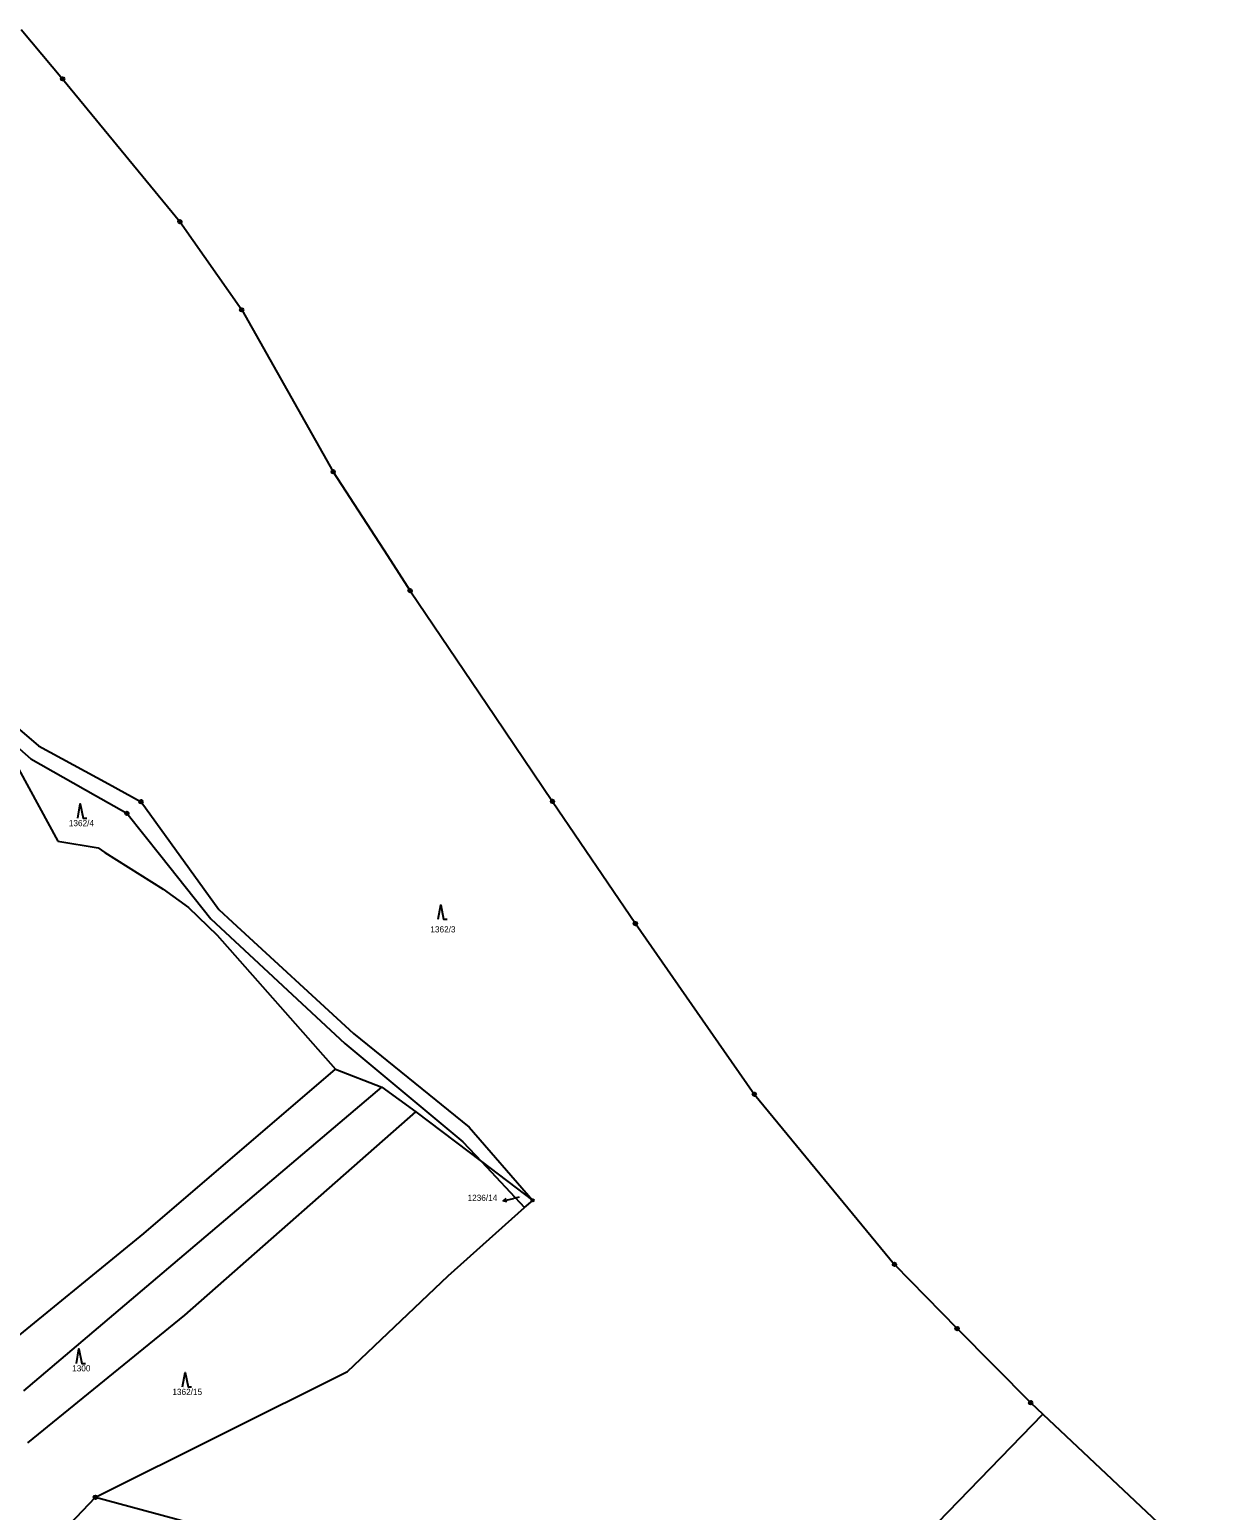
# Model space of a CAD drawing. Extents: x -763205 to -760228, y -1155311 to -1152844.
# Drawn here: x -760828.3 to -760502.3, y -1154305.4 to -1153896.1 of the extents above; entities that cross this region are included whole.
import ezdxf

# ---------------------------------------------------------------- set-up
doc = ezdxf.new("R2010")
doc.units = 0
for name, color, linetype in [('Vrstva 1', 7, 'Continuous'), ('Vrstva 13', 7, 'Continuous'), ('Vrstva 16', 7, 'Continuous'), ('Vrstva 18', 7, 'Continuous'), ('Vrstva 24', 7, 'Continuous'), ('Vrstva 25', 7, 'Continuous'), ('Vrstva 6', 7, 'Continuous')]:
    doc.layers.add(name, color=color, linetype=linetype)

msp = doc.modelspace()

# ---------------------------------------------------------------- linework, layer by layer
at = {"layer": 'Vrstva 1'}
for p, q in [((-760860.08, -1154069.56), (-760827.94, -1154097.7)), ((-760848.01, -1154074.98), (-760825.8, -1154094.1)), ((-760825.8, -1154094.1), (-760806.51, -1154104.61)), ((-760827.94, -1154097.7), (-760810.06, -1154107.81)), ((-760806.51, -1154104.61), (-760797.48, -1154109.54)), ((-760810.06, -1154107.81), (-760801.37, -1154112.73)), ((-760797.48, -1154109.54), (-760775.97, -1154139.3)), ((-760801.37, -1154112.73), (-760792.01, -1154124.48)), ((-760792.01, -1154124.48), (-760778.15, -1154141.89)), ((-760775.97, -1154139.3), (-760772.17, -1154142.8)), ((-760778.15, -1154141.89), (-760741.14, -1154176.34)), ((-760772.17, -1154142.8), (-760738.75, -1154173.58)), ((-760741.14, -1154176.34), (-760708.6, -1154203.49)), ((-760738.75, -1154173.58), (-760706.84, -1154199.49)), ((-760706.84, -1154199.49), (-760689.28, -1154219.7)), ((-760708.6, -1154203.49), (-760703.46, -1154208.97)), ((-760703.46, -1154208.97), (-760691.56, -1154221.65)), ((-760691.56, -1154221.65), (-760689.28, -1154219.7))]:
    msp.add_line(p, q, dxfattribs=at)
at = {"layer": 'Vrstva 13'}
for p, q in [((-760830.59, -1153896.11), (-760819.16, -1153909.72)), ((-760819.16, -1153909.72), (-760786.73, -1153949.18)), ((-760786.73, -1153949.18), (-760769.67, -1153973.56)), ((-760769.67, -1153973.56), (-760744.4, -1154018.31)), ((-760744.4, -1154018.31), (-760729.42, -1154041.48)), ((-760729.42, -1154041.48), (-760723.14, -1154051.19)), ((-760723.14, -1154051.19), (-760699.65, -1154085.96)), ((-760699.65, -1154085.96), (-760683.8, -1154109.44)), ((-760683.8, -1154109.44), (-760660.89, -1154143.21)), ((-760660.89, -1154143.21), (-760636.5, -1154178.24)), ((-760636.5, -1154178.24), (-760628.04, -1154190.4)), ((-760628.04, -1154190.4), (-760589.33, -1154237.4)), ((-760589.33, -1154237.4), (-760572.03, -1154255.15)), ((-760572.03, -1154255.15), (-760551.7, -1154275.64)), ((-760551.7, -1154275.64), (-760548.38, -1154278.77)), ((-760548.38, -1154278.77), (-760502.34, -1154322.12))]:
    msp.add_line(p, q, dxfattribs=at)
at = {"layer": 'Vrstva 16'}
for p in [(-760697.48, -1154219.847), (-760692.97, -1154218.79)]:
    msp.add_line(p, (-760694.56, -1154219.16), dxfattribs=at)
msp.add_lwpolyline([(-760696.392, -1154220.105), (-760697.48, -1154219.847), (-760696.621, -1154219.132)], dxfattribs=at)
at = {"layer": 'Vrstva 24'}
for centre, radius in [((-760819.16, -1153909.72), 0.5), ((-760819.16, -1153909.72), 0.1), ((-760786.73, -1153949.18), 0.5), ((-760786.73, -1153949.18), 0.1), ((-760769.67, -1153973.56), 0.5), ((-760769.67, -1153973.56), 0.1), ((-760744.4, -1154018.31), 0.5), ((-760744.4, -1154018.31), 0.5), ((-760744.4, -1154018.31), 0.1), ((-760744.4, -1154018.31), 0.1), ((-760723.14, -1154051.19), 0.5), ((-760723.14, -1154051.19), 0.1), ((-760797.48, -1154109.54), 0.5), ((-760797.48, -1154109.54), 0.1), ((-760683.8, -1154109.44), 0.5), ((-760683.8, -1154109.44), 0.1), ((-760801.37, -1154112.73), 0.5), ((-760801.37, -1154112.73), 0.1), ((-760660.89, -1154143.21), 0.5), ((-760660.89, -1154143.21), 0.1), ((-760628.04, -1154190.4), 0.5), ((-760628.04, -1154190.4), 0.1), ((-760689.28, -1154219.7), 0.335), ((-760689.28, -1154219.7), 0.067), ((-760589.33, -1154237.4), 0.5), ((-760589.33, -1154237.4), 0.1), ((-760572.03, -1154255.15), 0.5), ((-760572.03, -1154255.15), 0.1), ((-760551.7, -1154275.64), 0.5), ((-760551.7, -1154275.64), 0.1), ((-760810.09, -1154301.76), 0.5), ((-760810.09, -1154301.76), 0.1)]:
    msp.add_circle(centre, radius, dxfattribs=at)
at = {"layer": 'Vrstva 25'}
for points in [[(-760814.95, -1154114.08), (-760814.25, -1154110.08), (-760813.45, -1154114.08), (-760812.45, -1154114.08)], [(-760715.4, -1154141.98), (-760714.7, -1154137.98), (-760713.9, -1154141.98), (-760712.9, -1154141.98)], [(-760815.35, -1154264.78), (-760814.65, -1154260.78), (-760813.85, -1154264.78), (-760812.85, -1154264.78)], [(-760786, -1154271.29), (-760785.3, -1154267.29), (-760784.5, -1154271.29), (-760783.5, -1154271.29)]]:
    msp.add_lwpolyline(points, dxfattribs=at)
at = {"layer": 'Vrstva 6'}
for p, q in [((-760833.66, -1154096.22), (-760820.42, -1154120.46)), ((-760820.42, -1154120.46), (-760809.3, -1154122.29)), ((-760809.3, -1154122.29), (-760807.47, -1154123.56)), ((-760807.47, -1154123.56), (-760791.32, -1154133.65)), ((-760791.32, -1154133.65), (-760784.4, -1154138.8)), ((-760784.4, -1154138.8), (-760776.45, -1154146.45)), ((-760776.45, -1154146.45), (-760743.78, -1154183.47)), ((-760796.67, -1154228.88), (-760743.78, -1154183.47)), ((-760743.78, -1154183.47), (-760730.96, -1154188.4)), ((-760829.81, -1154272.34), (-760730.96, -1154188.4)), ((-760730.96, -1154188.4), (-760721.56, -1154195.27)), ((-760785.34, -1154251.4), (-760721.56, -1154195.27)), ((-760721.56, -1154195.27), (-760703.46, -1154208.97)), ((-760703.46, -1154208.97), (-760689.28, -1154219.7)), ((-760712.66, -1154240.6), (-760691.56, -1154221.65)), ((-760942.66, -1154347.81), (-760796.67, -1154228.88)), ((-760740.44, -1154266.97), (-760712.66, -1154240.6)), ((-760828.72, -1154286.7), (-760785.34, -1154251.4)), ((-760810.09, -1154301.76), (-760740.44, -1154266.97)), ((-760609.35, -1154341.75), (-760548.38, -1154278.77)), ((-760820.62, -1154312.91), (-760810.09, -1154301.76)), ((-760810.09, -1154301.76), (-760751.67, -1154317.46))]:
    msp.add_line(p, q, dxfattribs=at)

# ---------------------------------------------------------------- texts
at = {"layer": 'Vrstva 16'}
msp.add_text('1236/14', height=1.7, dxfattribs=at).set_placement((-760707.271, -1154219.85))
at = {"layer": 'Vrstva 18'}
for s, height, p in [('1362/4', 1.7, (-760817.427, -1154116.28)), ('1362/3', 1.7, (-760717.547, -1154145.65)), ('1236/14', 0.1, (-760692.947, -1154218.79)), ('1300', 1.7, (-760816.507, -1154266.98)), ('1362/15', 1.7, (-760788.817, -1154273.49))]:
    msp.add_text(s, height=height, dxfattribs=at).set_placement(p)

doc.saveas('drawing.dxf')
